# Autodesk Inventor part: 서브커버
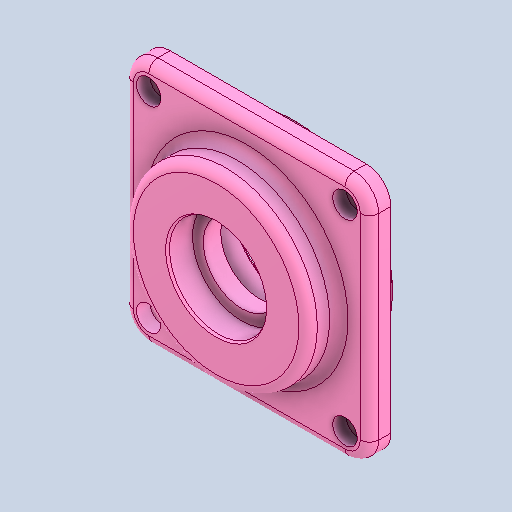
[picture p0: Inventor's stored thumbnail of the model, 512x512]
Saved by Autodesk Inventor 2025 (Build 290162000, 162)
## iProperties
Created: 2024-08
Part Number: 서브커버
Material: 일반
Document SubType Name: Modeling
Designer: rese9
Density: 1 g/cm^3
Appearance: 기본값
Author: jhkim
Sending System: Autodesk Inventor 2025
Preprocessor: ST-DEVELOPER v20
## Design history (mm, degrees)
feature "솔리드1"
node "솔리드2"
